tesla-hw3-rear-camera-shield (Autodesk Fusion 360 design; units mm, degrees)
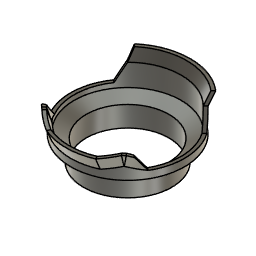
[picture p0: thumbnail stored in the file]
sketch "Sketch1" plane through (0, 0, 0) normal (0, 0, 1) x axis (1, 0, 0)
  circle C1 centre (0, 0) radius 8.5
  circle C2 centre (0, 0) radius 9.1
  point P1 (0, 0)
  point P2 (0, 0)
  coincident P1 P2
  concentric C1 C2
  dimension "d1" diameter C1 = 17
  dimension "d2" diameter C2 = 18.2
extrude "Extrude1" new body sketch "Sketch1" along normal blind 4
sketch "Sketch2" plane through (0, 0, 0) normal (0, 1, 0) x axis (1, 0, 0)
  line L1 (11.7, -4.9463) -> (9.1, -4)
  line L2 (9.1, -4) -> (-9.1, -4)
  line L3 (11.7, -6.4463) -> (11.7, -4.9463)
  line L4 (11, -6.4463) -> (11.7, -6.4463)
  line L5 (11, -5.4463) -> (11, -6.4463)
  line L6 (8.5, -4) -> (9.1, -4)
  line L7 (8.5, -4.2) -> (8.5, -4)
  line L8 (11, -5.4463) -> (8.5, -4.2)
  point P2 (9.1, -4)
  point P5 (9.1, -4)
  point P9 (9.1, -4)
  point P10 (8.5, -4)
  point P3 (11.7, -4.9463)
  point P6 (11.7, -6.4463)
  point P7 (11, -6.4463)
  point P1 (0, 0)
  point P8 (11, -5.4463)
  point P11 (8.5, -4.2)
  coincident P2 L2
  coincident P2 P5
  vertical L3
  perpendicular L3 L4
  perpendicular L4 L5
  coincident P5 P9
  coincident L2 P10
  parallel L2 L6
  perpendicular L6 L7
  dimension "d6" distance P9 P10 = 0.6
  dimension "d7" angle L1 L6 = 160
  dimension "d8" distance P3 P6 = 1.5
  dimension "d9" distance P6 P7 = 0.7
  dimension "d11" distance P1 P8 = 11
  dimension "d58" distance P10 P11 = 0.2
  dimension "d59" distance P3 P8 = 0.5
sweep "Sweep1" sketch "Sketch2" TwistAngle 0 TaperAngle 0
sketch "Sketch3" plane through (0, 0, 6.4463) normal (0, 0, 1) x axis (-1, 0, 0)
  line L1 (8.2731, -8.2731) -> (0, 0)
  line L2 (-8.2731, -8.2731) -> (0, 0)
  line L3 (0, -11.7) -> (0, 0)
  line L4 (0, 11.7) -> (0, 0)
  line L5 (4.9446, 10.6038) -> (0, 0)
  line L6 (-4.9446, 10.6038) -> (0, 0)
  line L7 (10.1325, 5.85) -> (0, 0)
  line L8 (-10.1325, 5.85) -> (0, 0)
  circle C1 centre (0, 0) radius 11.7
  circle C2 centre (0, 0) radius 11
  point P1 (0, 0)
  point P3 (0, 0)
  point P4 (8.2731, -8.2731)
  point P5 (-8.2731, -8.2731)
  point P6 (0, 0)
  point P7 (0, -11.7)
  point P8 (0, 11.7)
  point P9 (0, 0)
  point P10 (4.9446, 10.6038)
  point P11 (-4.9446, 10.6038)
  point P2 (0, 0)
  point P12 (0, 0)
  point P13 (10.1325, 5.85)
  point P14 (-10.1325, 5.85)
  coincident P1 P3
  coincident C1 P4
  coincident C1 P5
  coincident P1 P6
  coincident C1 P7
  vertical L3
  coincident C1 P8
  parallel L3 L4
  coincident P1 P9
  coincident C1 P10
  coincident C1 P11
  coincident P2 P12
  coincident C1 P13
  coincident C1 P14
  dimension "d18" angle L1 L3 = 45
  dimension "d19" angle L2 L3 = 45
  dimension "d35" angle L4 L6 = 25
  dimension "d36" angle L4 L8 = 60
  dimension "d37" angle L4 L5 = 25
  dimension "d39" angle L4 L7 = 60
extrude "Extrude2" add sketch "Sketch3" profile of C1 C2 L1 L2 L3 along normal blind 3.5
chamfer "Chamfer1" distance 2 distance 3.5
sketch "Sketch4" plane through (0, 0, 0) normal (1, 0, 0) x axis (0, 1, 0)
  line L1 (12.8547, 11.9463) -> (11.7, 9.9463)
  line L2 (12.1547, 11.9463) -> (12.8547, 11.9463)
  line L3 (11, 9.9463) -> (12.1547, 11.9463)
  line L4 (11.7, 9.9463) -> (11, 9.9463)
  line L5 (8.2731, 9.9463) -> (11.7, 9.9463)
  point P2 (11.7, 9.9463)
  point P7 (11.7, 9.9463)
  point P5 (11, 9.9463)
  point P6 (11, 9.9463)
  point P3 (12.8547, 11.9463)
  point P4 (12.1547, 11.9463)
  horizontal L2
  coincident P2 L5
  coincident P2 P7
  horizontal L4
  coincident P5 P6
  dimension "d24" distance P2 P6 = 0.7
  dimension "d25" angle L1 L4 = 120
  dimension "d34" distance P3 P4 = 0.7
  dimension "d60" distance P2 L2 = 2
sweep "Sweep2" sketch "Sketch4" TwistAngle 0 TaperAngle 0
extrude "Extrude3" add sketch "Sketch3" profile of C1 C2 L5 L6 L7 L8 along normal blind 1
chamfer "Chamfer2" distance 3.5 distance 1
sketch "Sketch5" plane through (0, 0, 0) normal (1, 0, 0) x axis (0, 1, 0)
  line L1 (-12.7, 8.8463) -> (-11.7, 6.4463)
  line L2 (-12, 8.8463) -> (-12.7, 8.8463)
  line L3 (-11, 6.4463) -> (-12, 8.8463)
  line L4 (-11.7, 6.4463) -> (-11, 6.4463)
  line L5 (-11.7, 6.4463) -> (-10.6038, 6.4463)
  point P2 (-11.7, 6.4463)
  point P7 (-11.7, 6.4463)
  point P5 (-11, 6.4463)
  point P4 (-12, 8.8463)
  point P3 (-12.7, 8.8463)
  horizontal L2
  horizontal L4
  coincident P2 P7
  dimension "d44" distance P2 P5 = 0.7
  dimension "d45" distance P4 P5 = 1
  dimension "d47" distance P3 P4 = 0.7
  dimension "d61" distance L2 L4 = 2.4
sweep "Sweep3" sketch "Sketch5" TwistAngle 0 TaperAngle 0
chamfer "Chamfer3" distance 2.4 distance 3
chamfer "Chamfer4" distance 2 distance 1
